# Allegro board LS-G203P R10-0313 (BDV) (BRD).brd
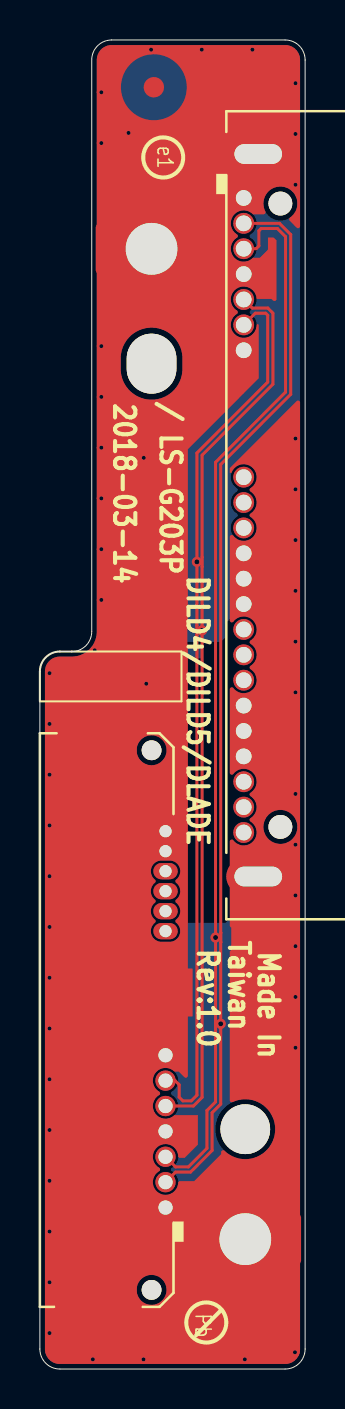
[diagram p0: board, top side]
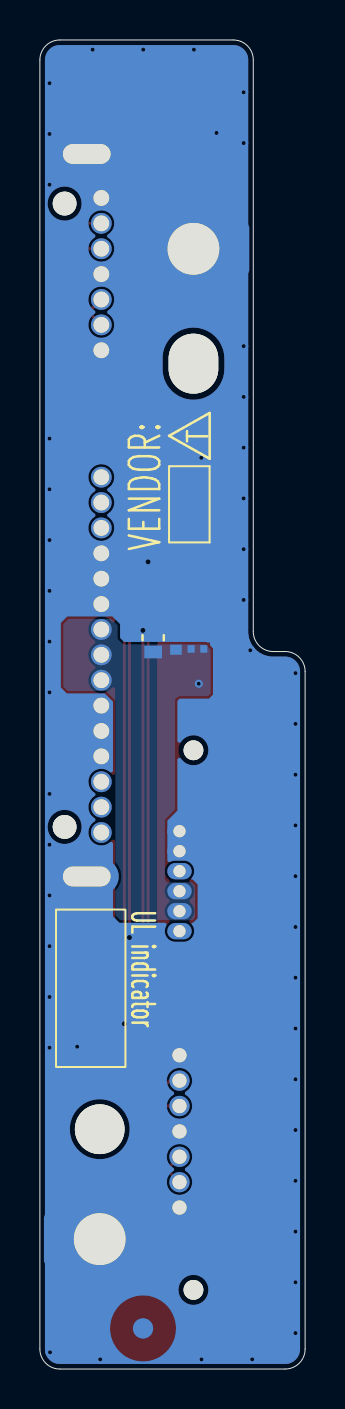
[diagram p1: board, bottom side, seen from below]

Outline 13.3 x 66.5 mm; copper layers: TOP, GND1, GND2, BOTTOM. Coordinates in mm from the lower left corner of the outline.
Outline path: 0,34.9 0,1 arc(0.29,0.29) 1,0 12.3,0 arc(13.01,0.29) 13.3,1 13.3,65.5 arc(13.01,66.21) 12.3,66.5 3.6,66.5 arc(2.89,66.21) 2.6,65.5 2.6,36.9 arc(2.31,36.19) 1.6,35.9 1,35.9 arc(0.29,35.61) 0,34.9

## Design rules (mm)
net group SATA_PRX_RC_DTX_1_C: nets SATA_PRX_RC_DTX_N1_C SATA_PRX_RC_DTX_P1_C
net group SATA_PTX_RC_DRX_1_C: nets SATA_PTX_RC_DRX_N1_C SATA_PTX_RC_DRX_P1_C

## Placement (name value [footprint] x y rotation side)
C232  0.1U_0201_10V K X5R  [C_0201]  5.08 36.03 90 bottom
C237  1000P_0402_50V7K  [C_0402]  6.48 35.99 90 bottom
C238  10U_0603_6.3V6M  [C_0603]  7.62 35.88 90 bottom
C239  0.1U_0201_10V K X5R  [C_0201]  5.71 36.03 90 bottom
FD1  CF  [FIDUCIAL_C40M80]  8.13 2.03 180 bottom
FD2  CF  [FIDUCIAL_C40M80]  5.71 64.14 0 top
H1  HOLEA  [H_2P6]  5.6 56.05 0 top
H2  HOLEA  [H_2P6]  10.3 6.5 0 top
H3  HOLEA  [H_2P5N]  10.3 12 0 top
H4  HOLEA  [H_2P5X3P0N]  5.6 50.3 0 top
JHDD1  SDAN_603008-022041  [SDAN_603008-022041_22P]  10.22 58.6 90 top
JODD1  SANTA_242002-2  [SANTA_242002-2_13P]  6.3 8.08 270 top
NOREF  -  []  0 0 0 top
NOREF#2  -  []  4.28 52.37 270 top
NOREF#3  -  []  -132.25 39.2 0 top
NOREF#4  -  []  0 0 0 top
NOREF#5  -  []  -12.87 -64.17 0 top
NOREF#6  -  []  -44.2 74.68 270 bottom
NOREF#7  -  []  -46.7 23.28 270 bottom
NOREF#8  -  []  -46.57 11.73 270 bottom

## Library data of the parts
C232 C239 = C_0201
C237 = C_0402
C238 = C_0603
FD1 FD2 = FIDUCIAL_C40M80
H1 H2 = H_2P6
H3 = H_2P5N
H4 = H_2P5X3P0N
JHDD1 = SDAN_603008-022041_22P
JODD1 = SANTA_242002-2_13P

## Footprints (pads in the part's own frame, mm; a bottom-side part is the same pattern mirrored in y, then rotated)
C_0201
  rect 0.381x0.356 smd: 1(0,0) 2(0.584,0)
C_0402
  rect 0.508x0.584 smd: 1(0,0) 2(0.914,0)
C_0603
  rect 0.635x0.889 smd: 1(0,0) 2(1.397,0)
FIDUCIAL_C40M80
  round 1.016 smd: 1(0,0)
H_2P5N
  round 2.489 hole 2.489 unplated: (0,0)
H_2P5X3P0N
  oval 2.489x2.997 hole 2.489x2.997 unplated: (0,0)
H_2P6
  round 3.099 hole 2.591: 1(0,0)
SANTA_242002-2_13P
  round 0.991 hole 0.991 unplated: (-22.88,-0.7) (4.12,-0.7)
  round 1.016 hole 0.711: 1(0,0) 2(-1.27,0) 3(-2.54,0) 4(-3.81,0) 5(-5.08,0) 6(-6.35,0) 7(-7.62,0)
  oval 0.813x1.219 hole 0.61: 8(-13.83,0) 9(-14.83,0) 10(-15.83,0) 11(-16.83,0) 12(-17.83,0) 13(-18.83,0)
  rect 2.591x3.683 smd: 14(-24.03,-3.3) 15(5.27,-3.3)
  rect 2.388x2.108 smd: 16(-10.76,0.3)
SDAN_603008-022041_22P
  round 1.194 hole 1.194 unplated: (-31.47,-1.84) (-0.28,-1.84)
  round 1.041 hole 0.787: 1(0,0) 2(-1.27,0) 3(-2.54,0) 4(-3.81,0) 5(-5.08,0) 6(-6.35,0) 7(-7.62,0) 8(-13.97,0) 9(-15.24,0) 10(-16.51,0) 11(-17.78,0) 12(-19.05,0) 13(-20.32,0) 14(-21.59,0) 15(-22.86,0) 16(-24.13,0) 17(-25.4,0) 18(-26.67,0) 19(-27.94,0) 20(-29.21,0) 21(-30.48,0) 22(-31.75,0)
  oval 1.803x3.2 hole 0.991x2.388: 23(-33.95,-0.73) 24(2.2,-0.73)

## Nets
+5V_ODD: C232.1 C237.1 C238.1 C239.1 JHDD1.14 JHDD1.15 JHDD1.16 JODD1.9 JODD1.10
GND: C232.2 C237.2 C238.2 C239.2 H1.1(TP-1) H2.1(TP-1) JHDD1.1 JHDD1.4 JHDD1.7 JHDD1.11 JHDD1.12 JHDD1.13 JHDD1.17 JHDD1.18 JHDD1.19 JHDD1.23 JHDD1.24 JODD1.1 JODD1.4 JODD1.7 JODD1.12 JODD1.13 JODD1.14 JODD1.15 JODD1.16
DP: JODD1.8
SATA_PRX_RC_DTX_N1_C: JHDD1.5 JODD1.5
SATA_PRX_RC_DTX_P1_C: JHDD1.6 JODD1.6
SATA_PTX_RC_DRX_N1_C: JHDD1.3 JODD1.3
SATA_PTX_RC_DRX_P1_C: JHDD1.2 JODD1.2

Pads without a net: FD1 1; FD2 1; JHDD1 8 9 10 20 21 22; JODD1 11

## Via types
v1: diameter 0.508, hole 0.254, TOP to BOTTOM, 4 vias
v2: diameter 0.457, hole 0.203, TOP to BOTTOM, 45 vias
v3: diameter 0.406, hole 0.203, TOP to BOTTOM, 4 vias

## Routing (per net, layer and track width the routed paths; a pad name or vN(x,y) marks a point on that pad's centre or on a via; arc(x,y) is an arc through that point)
+5V_ODD:
  vias: v3(5.33,34.29)
GND: length 247.4
  GND1 w0.203: JODD1.13 7.09,27.49 ; JODD1.13 5.51,26.33 ; JODD1.13 7.09,26.33 ; JODD1.13 5.51,27.49 ; JODD1.13 7.09,26.91 ; JODD1.13 6.3,27.49 ; JODD1.13 5.51,26.91 ; 9.67,30.11 JHDD1.19 ; JHDD1.19 10.92,30.66 ; JHDD1.19 10.77,30.11 ; JHDD1.19 10.77,31.2 ; JHDD1.19 9.52,30.66 ; JHDD1.19 9.67,31.2 ; JHDD1.1 10.22,59.29 ; JHDD1.1 9.67,58.05 ; JHDD1.1 10.77,59.14 ; JHDD1.1 10.92,58.6 ; JHDD1.1 9.52,58.6 ; JHDD1.1 9.67,59.14 ; JHDD1.1 10.77,58.05 ; 9.67,55.33 JHDD1.4 ; JHDD1.4 10.92,54.79 ; JHDD1.4 9.67,54.24 ; JHDD1.4 10.77,55.33 ; JHDD1.4 9.52,54.79 ; JHDD1.4 10.77,54.24 ; 4.33,57.32 H1.1 ; H1.1 5.6,57.78 ; H1.1 6.87,54.78 ; H1.1 6.87,57.32 ; H1.1 3.87,56.05 ; H1.1 7.33,56.05 ; H1.1 4.33,54.78 ; H1.1 5.6,54.32 ; JODD1.7 6.84,15.16 ; JODD1.7 6.99,15.7 ; JODD1.7 5.76,15.16 ; JODD1.7 6.3,16.39 ; JODD1.7 6.84,16.24 ; JODD1.7 5.76,16.24 ; JODD1.7 5.61,15.7 ; JHDD1.7 10.77,50.43 ; JHDD1.7 10.22,50.28 ; JHDD1.7 10.92,50.98 ; JHDD1.7 10.77,51.52 ; JHDD1.7 9.67,51.52 ; JHDD1.7 9.52,50.98 ; JHDD1.7 9.67,50.43 ; JHDD1.17 10.92,33.2 ; JHDD1.17 9.52,33.2 ; JHDD1.17 9.67,32.65 ; JHDD1.17 9.67,33.74 ; JHDD1.17 10.77,32.65 ; JHDD1.17 10.77,33.74 ; JHDD1.12 10.77,39 ; JHDD1.12 10.92,39.55 ; JHDD1.12 9.67,40.09 ; JHDD1.12 10.77,40.09 ; JHDD1.12 9.67,39 ; JHDD1.12 9.52,39.55 ; H2.1 11.57,5.23 ; H2.1 9.03,5.23 ; H2.1 10.3,8.23 ; H2.1 10.3,4.77 ; H2.1 8.57,6.5 ; H2.1 11.57,7.77 ; H2.1 9.03,7.77 ; H2.1 12.03,6.5 ; 5.51,26.49 JODD1.12 ; JODD1.12 7.09,25.33 ; JODD1.12 5.51,25.33 ; JODD1.12 7.09,25.91 ; JODD1.12 5.51,25.91 ; JODD1.12 7.09,26.49 ; 10.95,23.59 JHDD1.23 ; JHDD1.23 12.7,25.7 ; JHDD1.23 9.2,23.59 ; JHDD1.23 9.2,25.7 ; JHDD1.23 12.7,24.65 ; JHDD1.23 9.2,24.65 ; JHDD1.23 12.7,23.59 ; JHDD1.23 10.95,25.7 ; 9.67,31.38 JHDD1.18 ; JHDD1.18 9.52,31.93 ; JHDD1.18 9.67,32.47 ; JHDD1.18 10.92,31.93 ; JHDD1.18 10.77,31.38 ; JHDD1.18 10.77,32.47 ; 6.3,7.39 JODD1.1 ; JODD1.1 6.84,8.62 ; JODD1.1 6.99,8.08 ; JODD1.1 6.84,7.54 ; JODD1.1 5.76,8.62 ; JODD1.1 5.76,7.54 ; JODD1.1 5.61,8.08 ; JODD1.4 6.84,12.43 ; JODD1.4 5.76,11.35 ; JODD1.4 6.99,11.89 ; JODD1.4 5.61,11.89 ; JODD1.4 6.84,11.35 ; JODD1.4 5.76,12.43 ; JHDD1.13 10.77,38.82 ; JHDD1.13 9.52,38.28 ; JHDD1.13 9.67,37.73 ; JHDD1.13 9.67,38.82 ; JHDD1.13 10.92,38.28 ; JHDD1.13 10.77,37.73 ; 9.52,40.82 JHDD1.11 ; JHDD1.11 9.67,41.36 ; JHDD1.11 10.92,40.82 ; JHDD1.11 10.77,41.36 ; JHDD1.11 9.67,40.27 ; JHDD1.11 10.77,40.27 ; 9.2,61.85 JHDD1.24 ; JHDD1.24 9.2,60.79 ; JHDD1.24 12.7,61.85 ; JHDD1.24 12.7,59.74 ; JHDD1.24 9.2,59.74 ; JHDD1.24 10.95,59.74 ; JHDD1.24 12.7,60.79 ; JHDD1.24 10.95,61.85
  GND2 w0.203: 9.2,60.79 JHDD1.24 ; JHDD1.24 9.2,61.85 ; JHDD1.24 10.95,61.85 ; JHDD1.24 10.95,59.74 ; JHDD1.24 12.7,61.85 ; JHDD1.24 9.2,59.74 ; JHDD1.24 12.7,59.74 ; JHDD1.24 12.7,60.79 ; 10.95,23.59 JHDD1.23 ; JHDD1.23 12.7,25.7 ; JHDD1.23 12.7,23.59 ; JHDD1.23 9.2,25.7 ; JHDD1.23 9.2,24.65 ; JHDD1.23 9.2,23.59 ; JHDD1.23 10.95,25.7 ; JHDD1.23 12.7,24.65 ; 9.52,40.82 JHDD1.11 ; JHDD1.11 10.77,40.27 ; JHDD1.11 9.67,40.27 ; JHDD1.11 9.67,41.36 ; JHDD1.11 10.77,41.36 ; JHDD1.11 10.92,40.82 ; 9.67,37.73 JHDD1.13 ; JHDD1.13 9.67,38.82 ; JHDD1.13 10.77,37.73 ; JHDD1.13 10.92,38.28 ; JHDD1.13 10.77,38.82 ; JHDD1.13 9.52,38.28 ; JODD1.13 7.09,27.49 ; JODD1.13 5.51,27.49 ; JODD1.13 5.51,26.91 ; JODD1.13 7.09,26.33 ; JODD1.13 7.09,26.91 ; JODD1.13 5.51,26.33 ; JODD1.13 6.3,27.49 ; JHDD1.1 10.77,59.14 ; JHDD1.1 9.52,58.6 ; JHDD1.1 9.67,58.05 ; JHDD1.1 10.22,59.29 ; JHDD1.1 9.67,59.14 ; JHDD1.1 10.92,58.6 ; JHDD1.1 10.77,58.05 ; JHDD1.12 10.77,39 ; JHDD1.12 9.52,39.55 ; JHDD1.12 9.67,39 ; JHDD1.12 9.67,40.09 ; JHDD1.12 10.77,40.09 ; JHDD1.12 10.92,39.55 ; JODD1.1 6.84,8.62 ; JODD1.1 6.84,7.54 ; JODD1.1 5.76,7.54 ; JODD1.1 5.76,8.62 ; JODD1.1 6.99,8.08 ; JODD1.1 5.61,8.08 ; JODD1.1 6.3,7.39 ; 10.3,4.77 H2.1 ; H2.1 10.3,8.23 ; H2.1 12.03,6.5 ; H2.1 8.57,6.5 ; H2.1 9.03,7.77 ; H2.1 9.03,5.23 ; H2.1 11.57,7.77 ; H2.1 11.57,5.23 ; JHDD1.7 10.77,50.43 ; JHDD1.7 10.22,50.28 ; JHDD1.7 9.67,51.52 ; JHDD1.7 10.77,51.52 ; JHDD1.7 10.92,50.98 ; JHDD1.7 9.67,50.43 ; JHDD1.7 9.52,50.98 ; JHDD1.4 10.77,55.33 ; JHDD1.4 10.77,54.24 ; JHDD1.4 9.67,55.33 ; JHDD1.4 9.67,54.24 ; JHDD1.4 9.52,54.79 ; JHDD1.4 10.92,54.79 ; 5.51,25.91 JODD1.12 ; JODD1.12 7.09,26.49 ; JODD1.12 7.09,25.91 ; JODD1.12 5.51,26.49 ; JODD1.12 7.09,25.33 ; JODD1.12 5.51,25.33 ; 3.87,56.05 H1.1 ; H1.1 5.6,57.78 ; H1.1 6.87,57.32 ; H1.1 6.87,54.78 ; H1.1 4.33,54.78 ; H1.1 4.33,57.32 ; H1.1 5.6,54.32 ; H1.1 7.33,56.05 ; JODD1.4 6.84,11.35 ; JODD1.4 6.99,11.89 ; JODD1.4 5.76,12.43 ; JODD1.4 6.84,12.43 ; JODD1.4 5.61,11.89 ; JODD1.4 5.76,11.35 ; JHDD1.18 10.92,31.93 ; JHDD1.18 10.77,32.47 ; JHDD1.18 9.67,31.38 ; JHDD1.18 9.52,31.93 ; JHDD1.18 9.67,32.47 ; JHDD1.18 10.77,31.38 ; JHDD1.17 10.77,32.65 ; JHDD1.17 9.67,33.74 ; JHDD1.17 10.77,33.74 ; JHDD1.17 9.52,33.2 ; JHDD1.17 9.67,32.65 ; JHDD1.17 10.92,33.2 ; 5.61,15.7 JODD1.7 ; JODD1.7 5.76,16.24 ; JODD1.7 6.84,15.16 ; JODD1.7 5.76,15.16 ; JODD1.7 6.84,16.24 ; JODD1.7 6.3,16.39 ; JODD1.7 6.99,15.7 ; 9.52,30.66 JHDD1.19 ; JHDD1.19 10.92,30.66 ; JHDD1.19 9.67,30.11 ; JHDD1.19 10.77,30.11 ; JHDD1.19 9.67,31.2 ; JHDD1.19 10.77,31.2
  vias: v2(0.48,34.82) v2(0.48,32.28) v2(0.48,29.74) v2(0.48,27.2) v2(0.48,24.66) v2(0.48,22.12) v2(0.48,19.58) v2(0.48,17.04) v2(0.48,14.5) v2(0.48,11.96) v2(0.48,9.42) v2(0.48,6.88) v2(0.48,4.34) v2(0.48,1.8) v2(2.66,0.48) v2(2.75,35.96) v2(3.08,63.88) v2(3.08,61.34) v2(3.08,51.18) v2(3.08,48.64) v2(3.08,46.1) v2(3.08,43.56) v2(3.08,41.02) v2(3.08,38.48) v2(5.2,0.48) v2(5.58,66.02) v2(8.12,66.02) v2(10.28,0.48) v2(10.66,66.02) v2(12.82,64.34) v2(12.82,61.8) v2(12.82,59.26) v2(12.82,46.56) v2(12.82,44.02) v2(12.82,41.48) v2(12.82,38.94) v2(12.82,36.4) v2(12.82,33.86) v2(12.82,28.78) v2(12.82,26.24) v2(12.82,23.7) v2(12.82,21.16) v2(12.82,18.62) v2(12.82,16.08) v2(12.79,0.84) v3(4.45,61.85) v3(5.21,45.59) v3(11.43,16.13)
SATA_PRX_RC_DTX_N1_C: length 44.5
  TOP w0.147: JHDD1.5 10.65,53.09 11.43,53.09 11.68,52.83 11.68,49.28 8.13,45.73 8.13,40.63 8.14,40.62 8.14,40.15 8.13,40.14 v1(8.13,36.96) 8.13,13.59 7.7,13.16 JODD1.5
SATA_PRX_RC_DTX_P1_C: length 44.5
  TOP w0.147: JHDD1.6 10.8,52.83 11.32,52.83 11.42,52.72 11.42,49.38 7.87,45.83 v1(7.87,40.39) 7.87,37.2 7.87,37.19 7.87,36.72 7.87,36.71 7.87,13.7 7.59,13.42 7.17,13.42 6.99,13.6 6.99,14.22 6.78,14.43 JODD1.6
SATA_PTX_RC_DRX_N1_C: length 53.1
  TOP w0.147: JHDD1.3 10.84,56.06 10.98,56.19 10.98,56.95 11.09,57.07 11.91,57.07 12.32,56.66 12.32,48.88 8.81,45.37 v1(8.81,21.59) 8.81,17.51 8.8,17.51 8.8,17.03 8.81,17.03 8.81,13.37 8.38,12.93 8.38,11.04 7.45,10.11 6.81,10.11 JODD1.3
SATA_PTX_RC_DRX_P1_C: length 53
  TOP w0.147: JHDD1.2 12.02,57.33 12.58,56.76 12.58,48.77 9.07,45.26 9.07,21.83 9.07,21.83 9.07,21.35 9.07,21.35 v1(9.07,17.27) 9.07,13.26 8.64,12.83 8.64,10.94 7.55,9.86 6.81,9.86 JODD1.2

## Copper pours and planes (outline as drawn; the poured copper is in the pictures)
+5V_ODD on BOTTOM: 9.85,37.53 11.88,37.53 12.12,37.28 12.12,34.16 11.89,33.93 9.99,33.93 9.51,33.44 9.51,22.7 9.26,22.45 5.66,22.45 5.51,22.6 5.51,24.19 5.68,24.36 6.92,24.36 7.03,24.47 7.03,27.49 6.53,27.99 6.53,33.48 6.34,33.67 4.87,33.67 4.75,33.79 4.75,36.01 4.99,36.25 9.13,36.25 9.4,36.53 9.4,37.22 9.72,37.54 9.85,37.54
GND on TOP (solid shape): outline of 1511 points within 0.25,0.25 13.05,66.25
GND on BOTTOM (solid shape): outline of 1469 points within 0.25,0.25 13.05,66.25
GND on GND1, GND2: 1,0.25 0.47,0.47 0.25,1 0.25,34.9 0.47,35.43 1,35.65 1.6,35.65 2.49,36.01 2.85,36.9 2.85,65.5 3.07,66.03 3.6,66.25 12.3,66.25 12.83,66.03 13.05,65.5 13.05,1 12.83,0.47 12.3,0.25

Small or netless copper shapes (teardrops, artwork), in the pictures only: 2 on TOP, 2 on BOTTOM

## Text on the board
User.Comments: DILD4/ DILD5/ DLADE | LSG203P | 2019-03-14 | 2018-03-14 | quill | 1.0
Ref Des/Silkscreen Top: / LS-G203P | Taiwan
PAGE_OUTLINE: LAYER | NAME | L3 | L2 | L4 | L5 | L1 | L6 | LA-D708P | DUMMY-COOPER | BOT(50 ohm) | GND1 | GND2 | LS-C701P | TOP | BOT(90 ohm) | LS-C703P | VCC | GND | L7 | L9 | L8 | L10 | L11 | L12 | L13 | L14 | LA-XXXXP | LS-XXXXP | LA-D581P | LA-C602P | LA-D751P | IN1(50 ohm) | LS-C706P | IN2(85 ohm) | BOT | LS-D581P | LS-C601P | LS-D751P | IN1 | LS-D701P | TOP(50 ohm) | LS-D582P | LS-C602P | LS-D752P | IN2 | GND3 | IN3 | IN2(50,85 ohm) | BOT(50,85 ohm) | LS-D702P | LS-D754P | BOT(85 ohm) | TOP(85 ohm) | LS-C603P | LS-D757P | LS-D758P | TOP(50,85 ohm) | LS-D759P | GND4 | LS-D75AP | LS-D75BP | LS-D75CP | LS-D75DP
User.34: GND4
User.35: GND5
User.36: FIGURE | SIZE | 8.0 | 24.0 | 28.0 | 31.0 | 102.0 | 39.0 | 47.0 | 98.0 | 94.0x39.0 | 122.0x102.0 | DRILL CHART: TOP to BOTTOM | ALL UNITS ARE IN MILS | TOLERANCE | +3.0/-3.0 | +2.0/-2.0 | PLATED | NON-PLATED | QTY | 45 | 6 | 7 | 22 | 2 | 1
User.37: 0 5_0 6_0 75_0 8_0 9_1 0_1 2_1 4_1 45_1 6-4L(5mils 55 ohm)-stack-up-160906 | 5.8/4.4
